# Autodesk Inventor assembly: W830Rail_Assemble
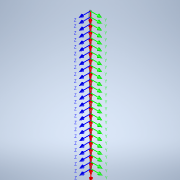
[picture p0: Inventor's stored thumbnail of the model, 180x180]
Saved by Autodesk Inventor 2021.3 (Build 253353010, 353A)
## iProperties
Created: 2021-11
Part Number: W830Rail_Assemble
Document SubType Name: Assembly
Designer: u1426
Author: u1426
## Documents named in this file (5)
- S:\Bridge_CADD\Other\SampleBridgeInventor\W830Rail_Assemble.iam
- S:\Bridge_CADD\Other\SampleBridgeInventor\W830Curb.ipt
- S:\Bridge_CADD\Other\SampleBridgeInventor\AISC - 6 x 3 x 1_4 - 125 - End.ipt
- S:\Bridge_CADD\Other\SampleBridgeInventor\AISC - 6 x 4 x 1_4 - 125 - End.ipt
- S:\Bridge_CADD\Other\SampleBridgeInventor\W830Post-Slab.iam
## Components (29 placed, 4 different names)
1. W830Curb:1 — Mate:3, Mate:4, Flush:1, Mate:5, Mate:6, Flush:2, Mate:7, Mate:8, Flush:3, Mate:9, Mate:10, Flush:4, Mate:16, Mate:17, Mate:18, Flush:7, Mate:19, Mate:20
2. AISC - 6 x 3 x 1_4 - 125 - End:1 — Mate:3, Mate:4, Flush:1
3. AISC - 6 x 3 x 1_4 - 125 - End:2 — Mate:7, Mate:8, Flush:3
4. AISC - 6 x 4 x 1_4 - 125 - End:1 — Mate:5, Mate:6, Flush:2
5. AISC - 6 x 4 x 1_4 - 125 - End:2 — Mate:9, Mate:10, Flush:4
6. W830Post-Slab:1 [sub-assembly] — Mate:16, Mate:19
7. W830Post-Slab:2 [sub-assembly]
8. W830Post-Slab:3 [sub-assembly]
9. W830Post-Slab:4 [sub-assembly]
10. W830Post-Slab:5 [sub-assembly]
11. W830Post-Slab:6 [sub-assembly]
12. W830Post-Slab:7 [sub-assembly]
13. W830Post-Slab:8 [sub-assembly]
14. W830Post-Slab:9 [sub-assembly]
15. W830Post-Slab:10 [sub-assembly]
16. W830Post-Slab:11 [sub-assembly]
17. W830Post-Slab:12 [sub-assembly]
18. W830Post-Slab:13 [sub-assembly]
19. W830Post-Slab:14 [sub-assembly]
20. W830Post-Slab:15 [sub-assembly]
21. W830Post-Slab:16 [sub-assembly]
22. W830Post-Slab:17 [sub-assembly]
23. W830Post-Slab:18 [sub-assembly]
24. W830Post-Slab:19 [sub-assembly]
25. W830Post-Slab:20 [sub-assembly]
26. W830Post-Slab:21 [sub-assembly]
27. W830Post-Slab:25 [sub-assembly]
28. W830Post-Slab:23 [sub-assembly] — Flush:8, Mate:20
29. W830Post-Slab:24 [sub-assembly]
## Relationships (19: Mate 13, Flush 6)
- Mate:3: W830Curb:1 ↔ AISC - 6 x 3 x 1_4 - 125 - End:1
- Mate:4: W830Curb:1 ↔ AISC - 6 x 3 x 1_4 - 125 - End:1
- Flush:1: W830Curb:1 ↔ AISC - 6 x 3 x 1_4 - 125 - End:1
- Mate:5: W830Curb:1 ↔ AISC - 6 x 4 x 1_4 - 125 - End:1
- Mate:6: W830Curb:1 ↔ AISC - 6 x 4 x 1_4 - 125 - End:1
- Flush:2: W830Curb:1 ↔ AISC - 6 x 4 x 1_4 - 125 - End:1
- Mate:7: W830Curb:1 ↔ AISC - 6 x 3 x 1_4 - 125 - End:2
- Mate:8: W830Curb:1 ↔ AISC - 6 x 3 x 1_4 - 125 - End:2
- Flush:3: W830Curb:1 ↔ AISC - 6 x 3 x 1_4 - 125 - End:2
- Mate:9: W830Curb:1 ↔ AISC - 6 x 4 x 1_4 - 125 - End:2
- Mate:10: W830Curb:1 ↔ AISC - 6 x 4 x 1_4 - 125 - End:2
- Flush:4: W830Curb:1 ↔ AISC - 6 x 4 x 1_4 - 125 - End:2
- Mate:16: W830Curb:1 ↔ W830Post-Slab:1
- Mate:17: W830Curb:1
- Mate:18: W830Curb:1
- Flush:7: W830Curb:1
- Mate:19: W830Curb:1 ↔ W830Post-Slab:1
- Flush:8: W830Post-Slab:23
- Mate:20: W830Curb:1 ↔ W830Post-Slab:23
